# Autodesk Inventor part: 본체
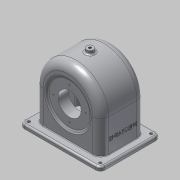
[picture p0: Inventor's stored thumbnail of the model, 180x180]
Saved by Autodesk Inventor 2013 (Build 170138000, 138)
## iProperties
Created: 2016-01
Part Number: 본체
Material: 알루미늄 6061
Document SubType Name: Modeling
Designer: dgall
Density: 2.71055 g/cm^3
Mass: 829 g
Surface Area: 1005.64 cm^2
Volume: 305.842 cm^3
Author: dgall
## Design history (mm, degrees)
sketch "스케치1"
  geometry: L1 (-57, 60.5)-(57, 60.5); L2 (57, 60.5)-(57, -60.5); L3 (57, -60.5)-(-57, -60.5); L4 (-57, -60.5)-(-57, 60.5); 1 further point
  constraints: 8 end point, 2 parallel, 1 horizontal, 1 perpendicular
  dimensions: "d6" = 121 distance between parallel lines of L3 L1; "d8" = 114 distance between parallel lines of L2 L4; "d9" = 57 distance from line of point (0, 0) L4 (= 0.5 x d8); "d10" = 60.5 distance from line of L1 point (0, 0) (= 0.5 x d6)
extrude "돌출1" new body sketch "스케치1" stored distance "d11" = 77; taper "d12" = 0 deg
sketch "스케치5"
  geometry: L1 (6, -5)-(108, -5); L2 (108, -5)-(108, -72); L3 (108, -72)-(6, -72); L4 (6, -72)-(6, -5); 1 further point
  constraints: 8 end point, 2 parallel, 1 horizontal, 1 perpendicular
  dimensions: "d21" = 67 distance between parallel lines of L3 L1; "d23" = 102 distance between parallel lines of L4 L2; "d24" = 51 distance from line of L4 point (57, -38.5) (= 0.5 x d23); "d25" = 33.5 distance from line of point (57, -38.5) L3 (= 0.5 x d21)
extrude "돌출2" cut sketch "스케치5" distance "d26" = 115; taper "d27" = 0 deg
fillet "모깎기3" dims "d28" = 57
fillet "모깎기4" dims "d29" = 51
sketch "스케치7"
  geometry: L1 (-33.5, 3.5)-(-33.5, 54.5) reference; L2 (-17.394, 28)-(-33.5, 41.514); L3 (0, 0)-(-62.083, 0); L4 (-17.394, 28)-(-17.394, 49.803); L5 (-38.5, 39.183)-(-35.5, 36.666); L6 (-38.5, 3.5)-(-38.5, 60.5) reference; L7 (-17.394, 28)-(-17.394, 20); L8 (-17.394, 20)-(-35.5, 20); L9 (-38.5, 39.183)-(-33.5, 41.514); L10 (-38.5, 3.5)-(-38.5, -60.5) reference; L11 (-35.5, 36.666)-(-35.5, 20)
  constraints: 16 end point, 3 perpendicular, 2 point on line
  dimensions: "d30" = 56 diameter of L2.start L3; "d32" = 50 deg angle of L4 L2; "d34" = 5 distance between parallel lines of L5 L2; "d39" = 40 diameter of L8 L3; "d42" = 21.10595 distance between parallel lines of L7 L6; "d45" = 3 distance between parallel lines of L6 L11
revolve "회전1" sketch "스케치7" stored, may be unused: angle "d40" = 90 deg
sketch "스케치8"
  geometry: L1 (-33.5, 41.514)-(-17.394, 28) reference; L2 (-38.5, 39.183)-(-35.5, 36.666); L3 (-38.5, 3.5)-(-38.5, 60.5) reference; L4 (0, 0)-(-53.932, 0); L5 (-35.5, 36.666)-(-35.5, 0); L6 (-38.5, 39.183)-(-38.5, 0); L7 (-38.5, 0)-(-35.5, 0)
  constraints: 10 end point, 4 point on line, 2 perpendicular, 1 collinear, 1 parallel
  dimensions: "d46" = 3 distance between parallel lines of L3 L5; "d47" = 5 distance between parallel lines of L1 L2
revolve "회전2" sketch "스케치8" stored, may be unused: angle "d48" = 90 deg
sketch "스케치9"
  geometry: C1 r 36.666 at (0, 0) reference; C2 r 20 at (0, 0)
  constraints: 1 centre point, 1 coincident
  dimensions: "d49" = 40 diameter of C2
extrude "돌출3" cut sketch "스케치9" distance "d51" = 20; taper "d52" = 0 deg
fillet "모깎기5" dims "d53" = 14
sketch "스케치10"
  geometry: C1 r 31 at (0, 0); 1 further point
  constraints: 1 centre point, 1 coincident
  dimensions: "d54" = 62 diameter of C1
extrude "돌출4" join sketch "스케치10" distance "d56" = 10; taper "d57" = 0 deg
sketch "스케치12"
  geometry: C1 r 31 at (0, 0) reference; C2 r 20 at (0, 0)
  constraints: 1 centre point, 1 coincident
  dimensions: "d58" = 40 diameter of C2
extrude "돌출5" cut sketch "스케치12" stored distance "d60" = 10; taper "d61" = 0 deg
sketch "스케치13"
  geometry: C1 r 36.666 at (0, 0) reference; A1 r 28 centre (0, 0) between (0, 28) and (-28, 0); 2 further points
  constraints: 4 point on circle, 1 centre point, 1 coincident
  dimensions: "d62" = 56 diameter of A1
hole "구멍1" sketch "스케치13" at (0, 28), (-28, 0), (0, -28), (28, 0) diameter "d64" = 2.459; stored, may be unused: countersink angle "d68" = 90 deg, drill point angle "d70" = 118 deg; dims "d65" = 7, "d66" = 4, "d67" = 2, "d69" = 9
sketch "스케치14"
  geometry: C1 r 31 at (0, 0) reference; A1 r 24 centre (0, 0) between (0, 24) and (-24, 0); 2 further points
  constraints: 4 point on circle, 1 centre point, 1 coincident
  dimensions: "d71" = 48 diameter of A1
hole "구멍2" sketch "스케치14" at (0, 24), (-24, 0), (0, -24), (24, 0) diameter "d73" = 2.459; stored, may be unused: countersink angle "d77" = 90 deg, drill point angle "d79" = 118 deg; dims "d74" = 6, "d75" = 4, "d76" = 2, "d78" = 8
chamfer "모따기1" distance "d80" = 1; stored, may be unused: second distance "d81" = 2, angle "d82" = 45 deg
node "작업 평면1"
sketch "스케치15"
  geometry: C1 r 6 at (-43, 38.5); 1 further point
  constraints: 1 centre point, 1 coincident
  dimensions: "d84" = 12 diameter of C1
extrude "돌출6" join sketch "스케치15" stored distance "d86" = 10; taper "d87" = 0 deg
sketch "스케치16"
  geometry: C1 r 6 at (0, 0) reference; 1 further point
  constraints: 1 coincident
hole "구멍3" sketch "스케치16" at (0, 0) diameter "d88" = 4.459; stored, may be unused: countersink angle "d92" = 90 deg, drill point angle "d94" = 118 deg; dims "d89" = 100, "d90" = 4, "d91" = 2, "d93" = 8
fillet "모깎기6" dims "d95" = 3
sketch "스케치17"
  geometry: L1 (-14, 63)-(-14, 14) reference; L2 (86, 0)-(0, 0) reference; L3 (100, 63)-(100, 14) reference; L4 (0, 77)-(86, 77) reference; L5 (-27, 90.5)-(113, 90.5); L6 (113, 90.5)-(113, -13.5); L7 (113, -13.5)-(-27, -13.5); L8 (-27, -13.5)-(-27, 90.5); A1 r 14 centre (0, 63) between (0, 77) and (-14, 63) reference; A2 r 14 centre (0, 14) between (-14, 14) and (0, 0) reference; A3 r 14 centre (86, 14) between (86, 0) and (100, 14) reference; A4 r 14 centre (86, 63) between (100, 63) and (86, 77) reference; 1 further point
  constraints: 8 end point, 2 parallel, 1 horizontal, 1 perpendicular
  dimensions: "d96" = 104 distance between parallel lines of L7 L5; "d98" = 140 distance between parallel lines of L6 L8; "d99" = 70 distance from line of point (43, 38.5) L8 (= 0.5 x d98); "d100" = 52 distance from line of point (43, 38.5) L5 (= 0.5 x d96)
extrude "돌출7" join sketch "스케치17" distance "d101" = 7; taper "d102" = 0 deg
fillet "모깎기7" dims "d103" = 8
fillet "모깎기8" dims "d104" = 3
sketch "스케치18"
  geometry: C1 r 2.5 at (-105, 82.5); C2 r 2.5 at (19, 82.5); C3 r 2.5 at (19, -5.5); C4 r 2.5 at (-105, -5.5); A1 r 5 centre (19, 82.5) between (24, 82.5) and (19, 87.5) reference; A2 r 5 centre (-105, 82.5) between (-105, 87.5) and (-110, 82.5) reference; A3 r 5 centre (-105, -5.5) between (-110, -5.5) and (-105, -10.5) reference; A4 r 5 centre (19, -5.5) between (19, -10.5) and (24, -5.5) reference; 1 further point
  constraints: 4 centre point, 4 coincident
  dimensions: "d105" = 5 diameter of C1; "d107" = 5 diameter of C2; "d108" = 5 diameter of C3; "d109" = 5 diameter of C4
extrude "돌출8" cut sketch "스케치18" stored distance "d110" = 7; taper "d111" = 0 deg
fillet "모깎기9" dims "d112" = 3
fillet "모깎기10" dims "d113" = 3
fillet "모깎기11" dims "d114" = 9
sketch "스케치20"
  geometry: 1 further point
sketch "스케치21"
  geometry: L1 (30.398, -0.387)-(30.398, 49.387); L2 (30.398, 49.387)-(37.602, 49.387); L3 (37.602, 49.387)-(37.602, -0.387); L4 (37.602, -0.387)-(30.398, -0.387); L5 (30.398, 24.5)-(37.602, 24.5); L6 (34, -0.387)-(34, 49.387); L7 (64, -19.5)-(64, 68.5) reference; L8 (0, -14)-(57, -14) reference; 1 further point
  constraints: 4 end point, 4 midpoint, 2 other
  dimensions: "d115" = 30 distance between parallel lines of L7 L6; "d116" = 38.5 distance between parallel lines of L8 L5
extrude "돌출9" join sketch "스케치21" distance "d117" = 0.5; taper "d118" = 0 deg
fillet "모깎기12" dims "d119" = 1
node "솔리드1"
other parameters: "d83" = -127
